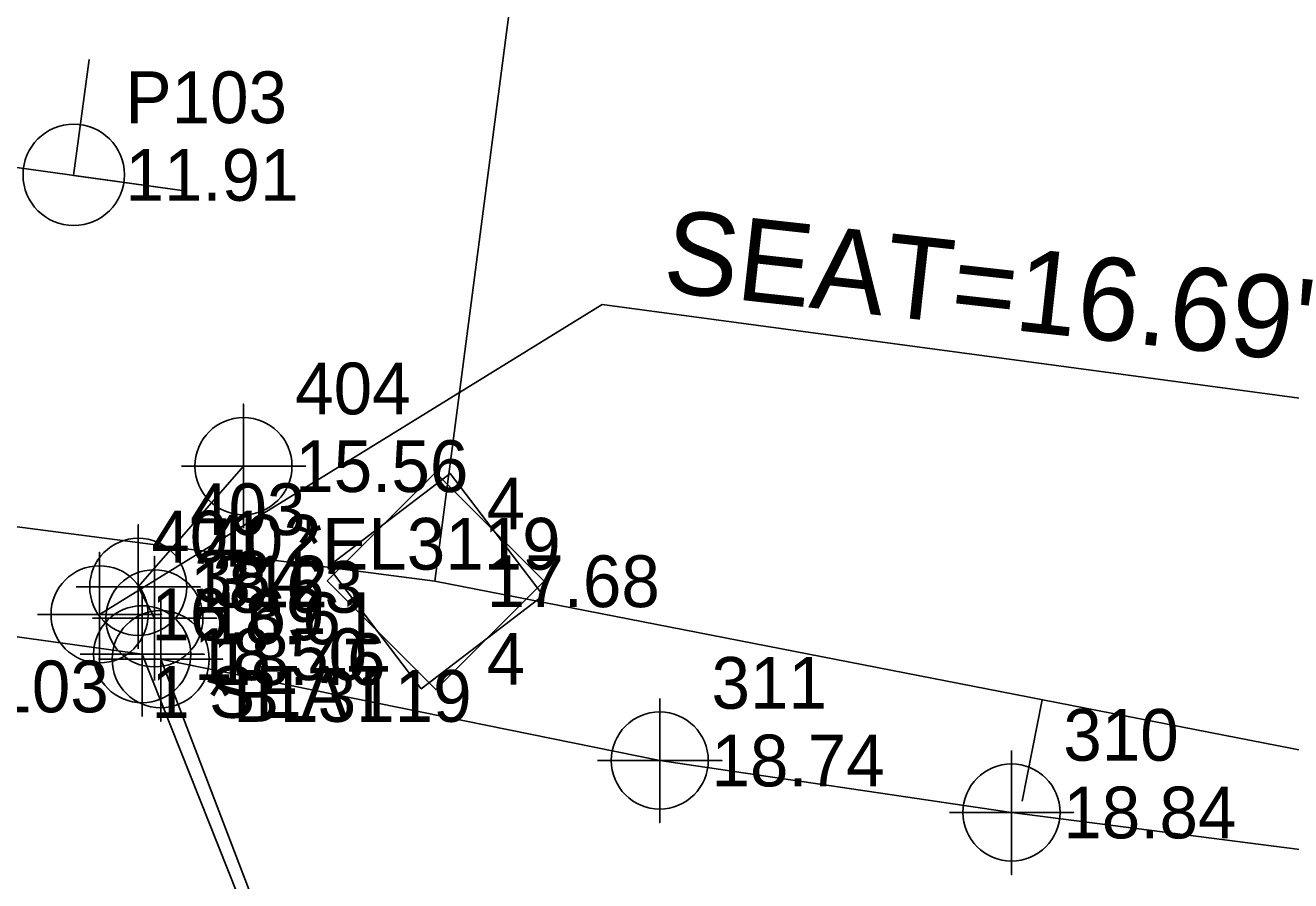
# Model space of a CAD drawing. Extents: x 2627243 to 2636458, y 566398 to 571062.
# Drawn here: x 2634660.8 to 2634722, y 569095 to 569136.3 of the extents above; entities that cross this region are included whole.
import ezdxf

# ---------------------------------------------------------------- set-up
doc = ezdxf.new("R2010")
doc.units = 0
for name, color, linetype in [('CTL Supplemental Horizontal and Vertical CELL', 7, 'Continuous'), ('CTL Supplemental Horizontal and Vertical Cogo Comment', 7, 'Continuous'), ('CTL Supplemental Horizontal and Vertical Cogo Elevation', 7, 'Continuous'), ('CTL Supplemental Horizontal and Vertical Cogo Number', 7, 'Continuous'), ('Exist Horizontal Baseline Alignment', 7, 'Continuous'), ('Exist Horizontal Baseline Alignment Station Label', 7, 'Continuous'), ('Exist Horizontal Baseline Alignment Tick small', 7, 'Continuous'), ('Exist Roads EOP', 7, 'Continuous'), ('Exist Roads EOP Cogo Elevation', 7, 'Continuous'), ('Exist Roads EOP Cogo Number', 7, 'Continuous'), ('Exist Roads EOP Cogo Point CELL', 7, 'Continuous'), ('Exist Structure Major Bridge Seam Cogo Comment', 7, 'Continuous'), ('Exist Structure Major Bridge Seat Cogo Comment', 7, 'Continuous'), ('Exist Structure Major Bridge Seat Cogo Elevation', 7, 'Continuous'), ('Exist Structure Major Bridge Seat Cogo Number', 7, 'Continuous'), ('Exist Structure Major Bridge Seat Cogo Point CELL', 7, 'Continuous'), ('Exist Structure Major Bridge Seat Top Elevation', 7, 'Continuous'), ('Exist Structure Major Bridge WW', 7, 'Continuous'), ('Exist Structure Major Bridge WW Cogo Comment', 7, 'Continuous'), ('Exist Structure Major Bridge WW Cogo Elevation', 7, 'Continuous'), ('Exist Structure Major Bridge WW Cogo Number', 7, 'Continuous'), ('Exist Structure Major Bridge WW Cogo Point CELL', 7, 'Continuous'), ('Exist Structure Major Deck Tunnel Box Culvert', 7, 'Continuous'), ('Exist Structure Major Deck Tunnel Box Culvert Cogo Elevation', 7, 'Continuous'), ('Exist Structure Major Deck Tunnel Box Culvert Cogo Number', 7, 'Continuous'), ('Exist Structure Major Deck Tunnel Box Culvert Cogo Point CELL', 7, 'Continuous'), ('Exist Utilities Power Joint Use Telephone CELL', 7, 'Continuous'), ('Exist Utilities Power Joint Use Telephone Cogo Elevation', 7, 'Continuous'), ('Exist Utilities Power Joint Use Telephone Cogo Number', 7, 'Continuous')]:
    doc.layers.add(name, color=color, linetype=linetype)

# ---------------------------------------------------------------- blocks, each defined once
blk = doc.blocks.new('CTL SUPPLEMENTAL HORIZONTAL AND VERTICAL')
at = {"layer": 'CTL Supplemental Horizontal and Vertical CELL'}
blk.add_line((0, 0), (0, 0), dxfattribs=at)
blk.add_lwpolyline([(-0.1043, 0.0004), (0.0005, 0.1052), (0.1055, 0.0002), (0.0007, -0.1047)], close=True, dxfattribs=at)
blk = doc.blocks.new('EXIST ROADS EOP COGO POINT')
at = {"layer": 'Exist Roads EOP Cogo Point CELL'}
blk.add_lwpolyline([(0, 0.06), (0, -0.06), (0, 0), (0.06, 0), (-0.06, 0)], dxfattribs=at)
blk.add_circle((0, 0), 0.0469, dxfattribs=at)
blk = doc.blocks.new('EXIST STRUCTURE MAJOR DECK TUNNEL BOX CULVERT COGO POINT')
at = {"layer": 'Exist Structure Major Deck Tunnel Box Culvert Cogo Point CELL'}
blk.add_lwpolyline([(-0.06, 0), (0.06, 0), (0, 0), (0, 0.06), (0, -0.06)], dxfattribs=at)
blk.add_circle((0, 0), 0.0469, dxfattribs=at)
blk = doc.blocks.new('EXIST STRUCTURE MAJOR BRIDGE SEAT COGO POINT')
at = {"layer": 'Exist Structure Major Bridge Seat Cogo Point CELL'}
blk.add_lwpolyline([(-0.06, 0), (0.06, 0), (0, 0), (0, 0.06), (0, -0.06)], dxfattribs=at)
blk.add_circle((0, 0), 0.0469, dxfattribs=at)
blk = doc.blocks.new('EXIST STRUCTURE MAJOR BRIDGE WW COGO POINT')
at = {"layer": 'Exist Structure Major Bridge WW Cogo Point CELL'}
blk.add_lwpolyline([(-0.06, 0), (0.06, 0), (0, 0), (0, 0.06), (0, -0.06)], dxfattribs=at)
blk.add_circle((0, 0), 0.0469, dxfattribs=at)
blk = doc.blocks.new('EXIST UTILITIES POWER JOINT USE TELEPHONE')
at = {"layer": 'Exist Utilities Power Joint Use Telephone CELL'}
blk.add_line((0, 0), (0, 0), dxfattribs=at)
blk.add_lwpolyline([(-0.1188, 0), (0.108, -0.0008), (0, -0.0004), (0, 0.1125)], dxfattribs=at)
blk.add_circle((0, 0.0001), 0.049, dxfattribs=at)

msp = doc.modelspace()

# ---------------------------------------------------------------- linework, layer by layer
at = {"layer": 'Exist Horizontal Baseline Alignment'}
for p, q in [((2634115.269, 569183.035), (2634680.61, 569109.426)), ((2634680.61, 569109.426), (2635129.789, 569021.834))]:
    msp.add_line(p, q, dxfattribs=at)
at = {"layer": 'Exist Horizontal Baseline Alignment Station Label'}
msp.add_line((2634688.25, 569168.104), (2634680.61, 569109.426), dxfattribs=at)
at = {"layer": 'Exist Horizontal Baseline Alignment Tick small'}
msp.add_line((2634709.944, 569103.706), (2634708.987, 569098.798), dxfattribs=at)
at = {"layer": 'Exist Roads EOP'}
msp.add_lwpolyline([(2634756.154, 569092.132), (2634708.467, 569098.258), (2634691.47, 569100.768), (2634667.356, 569105.661), (2634677.917, 569078.08), (2634688.445, 569077.775), (2634705.225, 569076.779), (2634739.193, 569072.427), (2634781.279, 569066.947)], dxfattribs=at)
at = {"layer": 'Exist Structure Major Bridge Seat Top Elevation'}
msp.add_lwpolyline([(2634664.402, 569107.828), (2634688.681, 569122.796), (2634731.011, 569117.111)], dxfattribs=at)
at = {"layer": 'Exist Structure Major Bridge WW'}
msp.add_lwpolyline([(2634667.054, 569107.636), (2634666.272, 569109.155), (2634671.356, 569114.987)], dxfattribs=at)
at = {"layer": 'Exist Structure Major Deck Tunnel Box Culvert'}
msp.add_lwpolyline([(2634565.456, 569119.889), (2634666.463, 569105.901), (2634677.512, 569078.102), (2634576.153, 569092.129), (2634565.524, 569119.463)], dxfattribs=at)

# ---------------------------------------------------------------- block references
at = {"layer": 'CTL Supplemental Horizontal and Vertical CELL', "xscale": 50, "yscale": 49.99999999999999, "rotation": -7.677818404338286}
msp.add_blockref('CTL SUPPLEMENTAL HORIZONTAL AND VERTICAL', (2634680.609, 569109.426), dxfattribs=at)
at = {"layer": 'CTL Supplemental Horizontal and Vertical CELL', "xscale": 50, "yscale": 50}
msp.add_blockref('CTL SUPPLEMENTAL HORIZONTAL AND VERTICAL', (2634680.61, 569109.426), dxfattribs=at)
at = {"layer": 'Exist Roads EOP Cogo Point CELL', "xscale": 50, "yscale": 50}
for p in [(2634667.356, 569105.661), (2634691.47, 569100.768), (2634708.467, 569098.258)]:
    msp.add_blockref('EXIST ROADS EOP COGO POINT', p, dxfattribs=at)
at = {"layer": 'Exist Structure Major Bridge Seat Cogo Point CELL', "xscale": 50, "yscale": 50}
msp.add_blockref('EXIST STRUCTURE MAJOR BRIDGE SEAT COGO POINT', (2634664.402, 569107.828), dxfattribs=at)
at = {"layer": 'Exist Structure Major Bridge WW Cogo Point CELL', "xscale": 50, "yscale": 50}
for p in [(2634671.356, 569114.987), (2634666.272, 569109.155), (2634667.054, 569107.636)]:
    msp.add_blockref('EXIST STRUCTURE MAJOR BRIDGE WW COGO POINT', p, dxfattribs=at)
at = {"layer": 'Exist Structure Major Deck Tunnel Box Culvert Cogo Point CELL', "xscale": 50, "yscale": 50}
msp.add_blockref('EXIST STRUCTURE MAJOR DECK TUNNEL BOX CULVERT COGO POINT', (2634666.463, 569105.901), dxfattribs=at)
at = {"layer": 'Exist Utilities Power Joint Use Telephone CELL', "xscale": 50, "yscale": 50.00000000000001, "rotation": -7.677818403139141}
msp.add_blockref('EXIST UTILITIES POWER JOINT USE TELEPHONE', (2634663.154, 569129.052), dxfattribs=at)

# ---------------------------------------------------------------- texts
at = {"layer": 'CTL Supplemental Horizontal and Vertical Cogo Comment'}
msp.add_text('4', height=2.5, dxfattribs=at).set_placement((2634683.109, 569104.426))
at = {"layer": 'CTL Supplemental Horizontal and Vertical Cogo Elevation'}
msp.add_text('17.68', height=2.5, dxfattribs=at).set_placement((2634683.109, 569108.176))
at = {"layer": 'CTL Supplemental Horizontal and Vertical Cogo Number'}
msp.add_text('4', height=2.5, dxfattribs=at).set_placement((2634683.109, 569111.926))
at = {"layer": 'Exist Roads EOP Cogo Elevation'}
for s, p in [('18.46', (2634669.856, 569104.411)), ('18.74', (2634693.97, 569099.518)), ('18.84', (2634710.967, 569097.008))]:
    msp.add_text(s, height=2.5, dxfattribs=at).set_placement(p)
at = {"layer": 'Exist Roads EOP Cogo Number'}
for s, p in [('312', (2634669.856, 569108.161)), ('311', (2634693.97, 569103.268)), ('310', (2634710.967, 569100.758))]:
    msp.add_text(s, height=2.5, dxfattribs=at).set_placement(p)
at = {"layer": 'Exist Structure Major Bridge Seam Cogo Comment'}
msp.add_text('*BL3103', height=2.5, dxfattribs=at).set_placement((2634652.021, 569103.095))
at = {"layer": 'Exist Structure Major Bridge Seat Cogo Comment'}
msp.add_text('1 SEAT', height=2.5, dxfattribs=at).set_placement((2634666.902, 569102.828))
at = {"layer": 'Exist Structure Major Bridge Seat Cogo Elevation'}
msp.add_text('16.69', height=2.5, dxfattribs=at).set_placement((2634666.902, 569106.578))
at = {"layer": 'Exist Structure Major Bridge Seat Cogo Number'}
msp.add_text('401', height=2.5, dxfattribs=at).set_placement((2634666.902, 569110.328))
at = {"layer": 'Exist Structure Major Bridge Seat Top Elevation'}
msp.add_text("SEAT=16.69'", height=4, rotation=353.69537, dxfattribs=at).set_placement((2634691.537, 569123.438))
at = {"layer": 'Exist Structure Major Bridge WW Cogo Comment'}
for s, p in [('*EL3119', (2634673.856, 569109.987)), ('*BL3119', (2634669.554, 569102.636))]:
    msp.add_text(s, height=2.5, dxfattribs=at).set_placement(p)
at = {"layer": 'Exist Structure Major Bridge WW Cogo Elevation'}
for s, p in [('15.56', (2634673.856, 569113.737)), ('18.63', (2634668.772, 569107.905)), ('18.61', (2634669.554, 569106.386))]:
    msp.add_text(s, height=2.5, dxfattribs=at).set_placement(p)
at = {"layer": 'Exist Structure Major Bridge WW Cogo Number'}
for s, p in [('404', (2634673.856, 569117.487)), ('403', (2634668.772, 569111.655)), ('402', (2634669.554, 569110.136))]:
    msp.add_text(s, height=2.5, dxfattribs=at).set_placement(p)
at = {"layer": 'Exist Structure Major Deck Tunnel Box Culvert Cogo Elevation'}
msp.add_text('18.50', height=2.5, dxfattribs=at).set_placement((2634668.963, 569104.651))
at = {"layer": 'Exist Structure Major Deck Tunnel Box Culvert Cogo Number'}
msp.add_text('384', height=2.5, dxfattribs=at).set_placement((2634668.963, 569108.401))
at = {"layer": 'Exist Utilities Power Joint Use Telephone Cogo Elevation'}
msp.add_text('11.91', height=2.5, dxfattribs=at).set_placement((2634665.654, 569127.802))
at = {"layer": 'Exist Utilities Power Joint Use Telephone Cogo Number'}
msp.add_text('P103', height=2.5, dxfattribs=at).set_placement((2634665.654, 569131.552))

doc.saveas('drawing.dxf')
